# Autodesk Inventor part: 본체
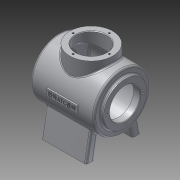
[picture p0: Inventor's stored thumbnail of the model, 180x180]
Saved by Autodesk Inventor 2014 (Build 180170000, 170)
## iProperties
Created: 2015-01
Part Number: 본체
Material: 알루미늄 6061
Document SubType Name: Modeling
Designer: basic
Density: 2.71 g/cm^3
Appearance: 알루미늄 - 평지
Mass: 1019.38 g
Surface Area: 1066.91 cm^2
Volume: 376.156 cm^3
Author: basic
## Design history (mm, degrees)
node "작업 평면1"
sketch "스케치5"
  geometry: C1 r 50 at (0, 0); 1 further point
  constraints: 1 centre point, 1 coincident
  dimensions: "d20" = 100 diameter of C1
extrude "돌출3" new body sketch "스케치5" distance "d21" = 112; taper "d22" = 0 deg
sketch "스케치6"
  geometry: C1 r 50 at (0, 0) reference; C2 r 38 at (0, 0)
  constraints: 1 centre point, 1 coincident
  dimensions: "d23" = 76 diameter of C2
extrude "돌출4" join sketch "스케치6" distance "d24" = 5; taper "d25" = 0 deg
sketch "스케치7"
  geometry: C1 r 38 at (0, 0) reference; 1 further point
  constraints: 1 vertical alignment
  dimensions: "d26" = 32 distance of C1.centre point (0, 32)
hole "구멍2" sketch "스케치7" at (0, 32) diameter "d27" = 3.242; stored, may be unused: countersink angle "d31" = 90 deg, drill point angle "d33" = 118 deg; dims "d28" = 8, "d29" = 4, "d30" = 2, "d32" = 10
sketch "스케치8"
  geometry: C1 r 50 at (0, 0) reference; C2 r 38 at (0, 0)
  constraints: 1 centre point, 1 coincident
  dimensions: "d37" = 76 diameter of C2
extrude "돌출5" join sketch "스케치8" distance "d38" = 5; taper "d39" = 0 deg
sketch "스케치9"
  geometry: C1 r 38 at (0, 0) reference; 1 further point
  constraints: 1 vertical alignment
  dimensions: "d40" = 32 distance of C1.centre point (0, 32)
hole "구멍3" sketch "스케치9" at (0, 32) diameter "d41" = 3.242; stored, may be unused: countersink angle "d45" = 90 deg, drill point angle "d47" = 118 deg; dims "d42" = 8, "d43" = 4, "d44" = 2, "d46" = 10
hole "구멍4" diameter "d53" = 54; stored, may be unused: countersink angle "d57" = 90 deg, drill point angle "d59" = 0 deg; dims "d51" = 10, "d52" = 10, "d54" = 8, "d55" = 4, "d56" = 2, "d58" = 10
fillet "모깎기1" dims "d60" = 3
sketch "스케치10"
  geometry: L1 (49, 0)-(49, 45); L2 (49, 45)-(-48, 45); L3 (-48, 45)-(-48, 0); L4 (-50, -33.621)-(-49.026, -32) reference; L5 (-49.026, -32)-(-50, -30.379) reference; L6 (-50, -30.379)-(-60, -30.379) reference; L7 (-60, -30.379)-(-60, -27) reference; L8 (-60, -27)-(62, -27) reference; L9 (62, -27)-(62, -30.379) reference; L10 (62, -30.379)-(52, -30.379) reference; L11 (52, -30.379)-(51.026, -32) reference; L12 (51.026, -32)-(52, -33.621) reference; L13 (52, -33.621)-(62, -33.621) reference; L14 (62, -33.621)-(62, -38) reference; L15 (62, -38)-(57, -38) reference; L16 (57, -38)-(57, -47) reference; L17 (54, -50)-(-52, -50) reference; L18 (-55, -47)-(-55, -38) reference; L19 (-55, -38)-(-60, -38) reference; L20 (-60, -38)-(-60, -33.621) reference; L21 (-60, -33.621)-(-50, -33.621) reference; L22 (-49.026, 32)-(-50, 33.621) reference; L23 (-50, 33.621)-(-60, 33.621) reference; L24 (-60, 33.621)-(-60, 38) reference; L25 (-60, 38)-(-55, 38) reference; L26 (-55, 38)-(-55, 47) reference; L27 (-52, 50)-(54, 50) reference; L28 (57, 47)-(57, 38) reference; L29 (57, 38)-(62, 38) reference; L30 (62, 38)-(62, 33.621) reference; L31 (62, 33.621)-(52, 33.621) reference; L32 (52, 33.621)-(51.026, 32) reference; L33 (51.026, 32)-(52, 30.379) reference; L34 (52, 30.379)-(62, 30.379) reference; L35 (62, 30.379)-(62, 27) reference; L36 (62, 27)-(-60, 27) reference; L37 (-60, 27)-(-60, 30.379) reference; L38 (-60, 30.379)-(-50, 30.379) reference; L39 (-50, 30.379)-(-49.026, 32) reference; L40 (-48, 0)-(49, 0); A1 r 3 centre (54, -47) between (54, -50) and (57, -47) reference; A2 r 3 centre (-52, -47) between (-55, -47) and (-52, -50) reference; A3 r 3 centre (-52, 47) between (-52, 50) and (-55, 47) reference; A4 r 3 centre (54, 47) between (57, 47) and (54, 50) reference; 3 further points
  constraints: 8 end point, 2 perpendicular, 1 coincident, 1 horizontal alignment, 1 midpoint, 1 parallel
  dimensions: "d61" = 97 distance of L3.end L1.start; "d64" = 7 distance between parallel lines of L26 L3; "d65" = 8 distance between parallel lines of L28 L1 (derived); "d66" = 90 diameter of L2 L40
revolve "회전1" sketch "스케치10" stored, may be unused: angle "d67" = 90 deg
node "작업 평면2"
sketch "스케치12"
  geometry: L1 (-39.336, -30.865)-(-48, -80); L2 (-48, -80)-(-34, -80); L3 (-34, -80)-(-27.282, -41.901); L4 (27.282, -41.901)-(34, -80); L5 (34, -80)-(48, -80); L6 (48, -80)-(39.336, -30.865); C1 r 45 at (0, 0) reference; A1 r 50 centre (0, 0) between (-39.336, -30.865) and (-27.282, -41.901) reference; 1 further point
  constraints: 12 end point, 4 point on circle, 3 equal length, 2 parallel, 1 collinear, 1 horizontal
  dimensions: "d72" = 14 distance of L1.end L2.end; "d73" = 100 deg angle of L1 L2; "d74" = 100 deg angle of L6 L5; "d75" = 96 distance of L5.end L1.end; "d79" = 80 distance from line of L2 point (0, 0)
extrude "돌출6" join sketch "스케치12" distance "d77" = 80; taper "d78" = 0 deg
node "작업 평면3"
sketch "스케치13"
  geometry: C1 r 38 at (0, 0); 1 further point
  constraints: 1 centre point, 1 coincident
  dimensions: "d81" = 76 diameter of C1
extrude "돌출7" join sketch "스케치13" stored distance "d82" = 80; taper "d83" = 0 deg
sketch "스케치14"
  geometry: C1 r 38 at (0, 0) reference; 1 further point
  constraints: 1 vertical alignment
  dimensions: "d84" = 32 distance of C1.centre point (0, 32)
hole "구멍5" sketch "스케치14" at (0, 32) diameter "d85" = 3.242; stored, may be unused: countersink angle "d89" = 90 deg, drill point angle "d91" = 118 deg; dims "d86" = 8, "d87" = 4, "d88" = 2, "d90" = 10
hole "구멍6" diameter "d97" = 54; stored, may be unused: countersink angle "d101" = 90 deg, drill point angle "d103" = 0 deg; dims "d95" = 10, "d96" = 10, "d98" = 8, "d99" = 4, "d100" = 2, "d102" = 50
node "작업 평면5"
sketch "스케치15"
  geometry: L1 (-27, 6)-(27, 6); L2 (27, 6)-(27, -6); L3 (27, -6)-(-27, -6); L4 (-27, -6)-(-27, 6); 3 further points
  constraints: 8 end point, 2 midpoint, 2 parallel, 1 horizontal, 1 horizontal alignment, 1 perpendicular, 1 vertical alignment
  dimensions: "d105" = 54 distance of L1.start L1.end; "d106" = 12 distance of L1.end L2.end
extrude "돌출8" join sketch "스케치15" stored distance "d107" = 80; taper "d108" = 0 deg
sketch "스케치16"
  geometry: 2 further points
  constraints: 1 coincident, 1 other
feature "엠보싱1" sketch "스케치16" dims "d60" = 3, "d109" = 0.5, "d110" = 0
fillet "모깎기2" dims "d111" = 3
chamfer "모따기1" distance "d112" = 1; stored, may be unused: second distance "d113" = 2, angle "d114" = 45 deg
fillet "모깎기3" dims "d115" = 3
fillet "모깎기4" dims "d116" = 3
fillet "모깎기5" dims "d117" = 3
fillet "모깎기6" dims "d118" = 3
node "솔리드2"
pattern_circular "원형 패턴2" dims angle "d35" = 360 deg
pattern_circular "원형 패턴3" dims angle "d49" = 360 deg
pattern_circular "원형 패턴4" dims angle "d93" = 360 deg
node "절단 모서리 투영2"
node "절단 모서리 투영4"
other parameters: "d19" = 55, "d71" = 39, "d80" = 62, "d104" = -52
